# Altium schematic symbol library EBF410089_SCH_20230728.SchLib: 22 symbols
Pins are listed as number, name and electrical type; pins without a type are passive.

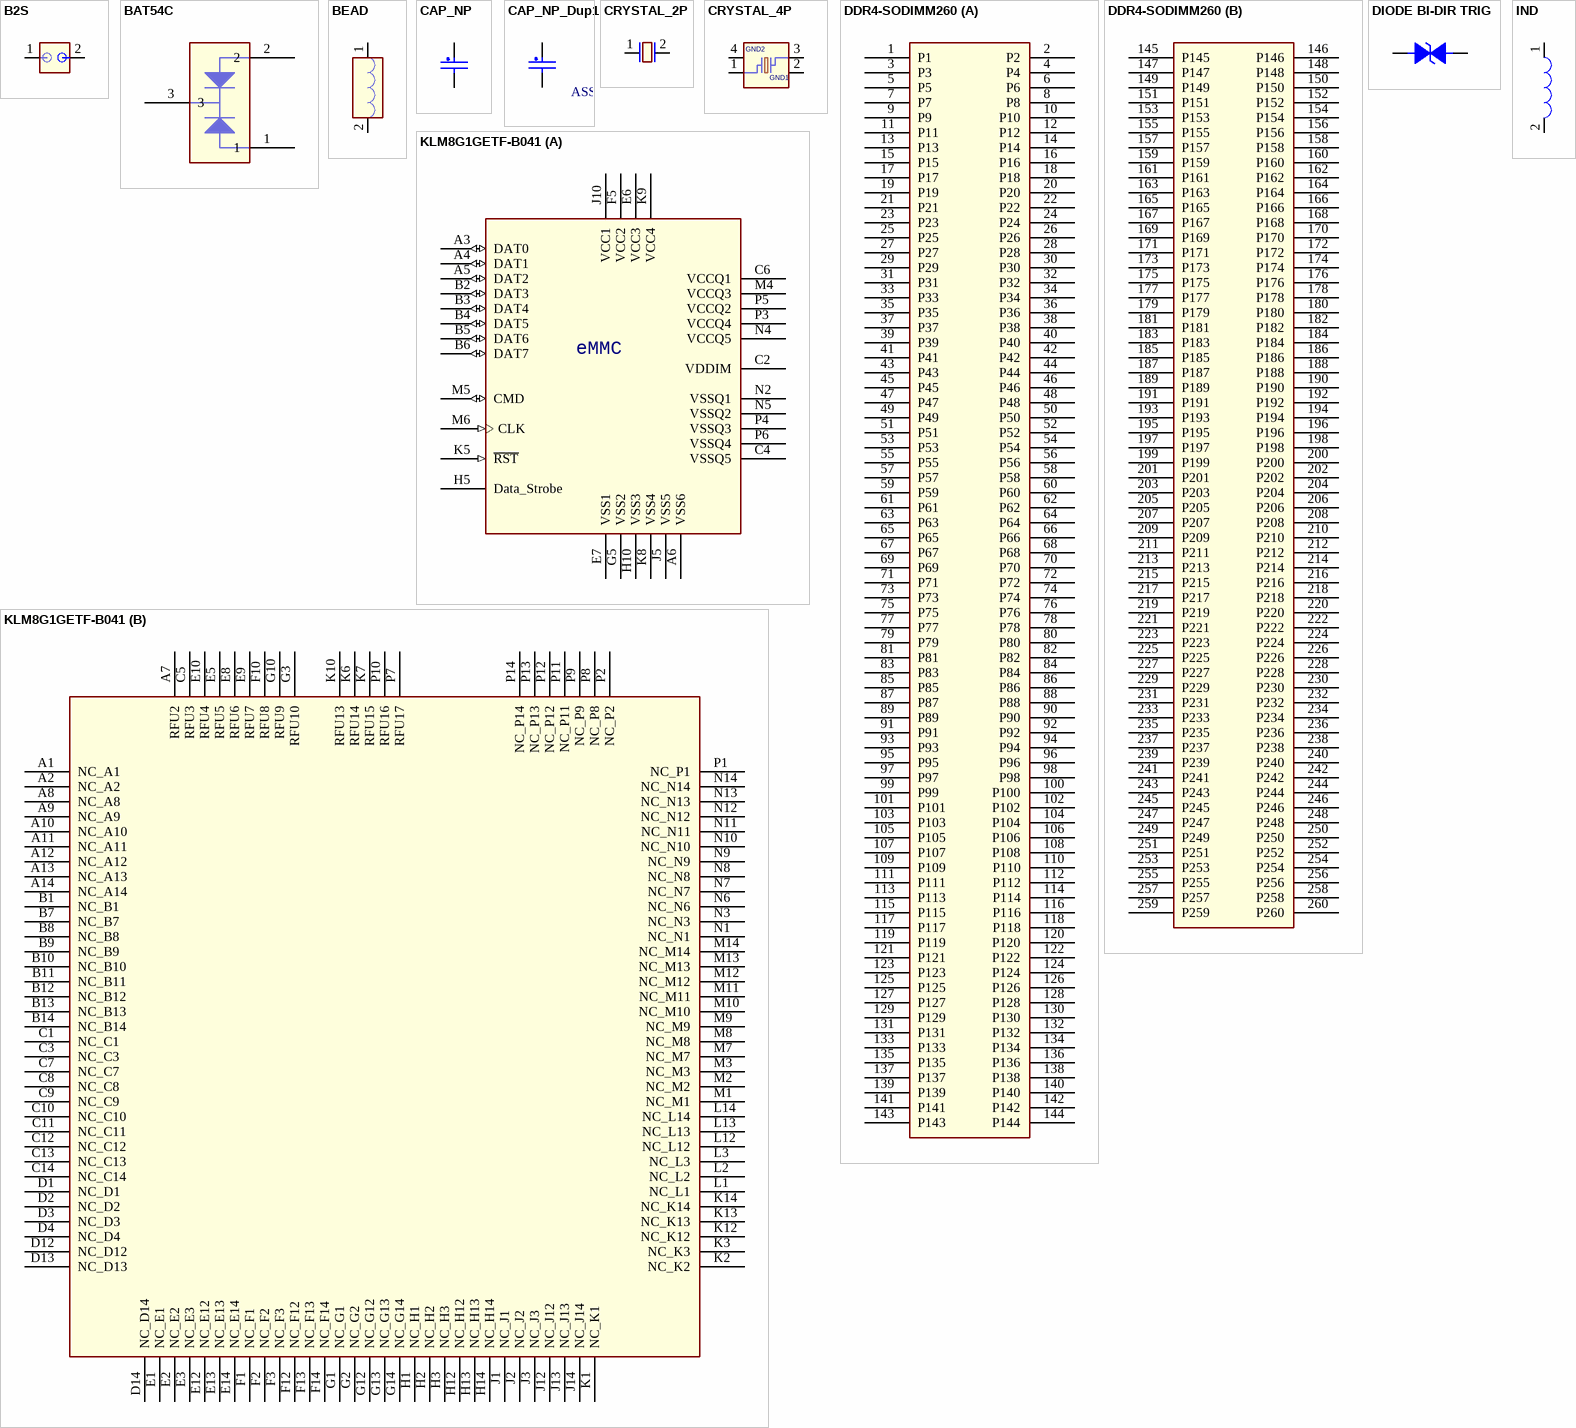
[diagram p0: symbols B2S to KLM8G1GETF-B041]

## B2S
designator J?
pins: 1, 2

## BAT54C
designator D?
footprint SOT23
pins: 1, 2, 3

## BEAD
designator L?
CLASS: DISCRETE
pins: 1, 2

## CAP_NP
designator C?
CLASS: DISCRETE
pins: 1, 2

## CAP_NP_Dup1
designator C?
CLASS: DISCRETE
pins: 1, 2

## CRYSTAL_2P
designator Y?
footprint 3215
pins: 1, 2

## CRYSTAL_4P
designator Y?
CLASS: IC
pins: 1, 2 GND1 (power), 3, 4 GND2 (power)

## DDR4-SODIMM260
designator J?
footprint SODIMMDDR4_260_0p5
part A pins: 1 P1, 2 P2, 3 P3, 4 P4, 5 P5, 6 P6, 7 P7, 8 P8, 9 P9, 10 P10, 11 P11, 12 P12, 13 P13, 14 P14, 15 P15, 16 P16, 17 P17, 18 P18, 19 P19, 20 P20, 21 P21, 22 P22, 23 P23, 24 P24, 25 P25, 26 P26, 27 P27, 28 P28, 29 P29, 30 P30, 31 P31, 32 P32, 33 P33, 34 P34, 35 P35, 36 P36, 37 P37, 38 P38, 39 P39, 40 P40, 41 P41, 42 P42, 43 P43, 44 P44, 45 P45, 46 P46, 47 P47, 48 P48, 49 P49, 50 P50, 51 P51, 52 P52, 53 P53, 54 P54, 55 P55, 56 P56, 57 P57, 58 P58, 59 P59, 60 P60, 61 P61, 62 P62, 63 P63, 64 P64, 65 P65, 66 P66, 67 P67, 68 P68, 69 P69, 70 P70, 71 P71, 72 P72, 73 P73, 74 P74, 75 P75, 76 P76, 77 P77, 78 P78, 79 P79, 80 P80, 81 P81, 82 P82, 83 P83, 84 P84, 85 P85, 86 P86, 87 P87, 88 P88, 89 P89, 90 P90, 91 P91, 92 P92, 93 P93, 94 P94, 95 P95, 96 P96, 97 P97, 98 P98, 99 P99, 100 P100, 101 P101, 102 P102, 103 P103, 104 P104, 105 P105, 106 P106, 107 P107, 108 P108, 109 P109, 110 P110, 111 P111, 112 P112, 113 P113, 114 P114, 115 P115, 116 P116, 117 P117, 118 P118, 119 P119, 120 P120, 121 P121, 122 P122, 123 P123, 124 P124, 125 P125, 126 P126, 127 P127, 128 P128, 129 P129, 130 P130, 131 P131, 132 P132, 133 P133, 134 P134, 135 P135, 136 P136, 137 P137, 138 P138, 139 P139, 140 P140, 141 P141, 142 P142, 143 P143, 144 P144
part B pins: 145 P145, 146 P146, 147 P147, 148 P148, 149 P149, 150 P150, 151 P151, 152 P152, 153 P153, 154 P154, 155 P155, 156 P156, 157 P157, 158 P158, 159 P159, 160 P160, 161 P161, 162 P162, 163 P163, 164 P164, 165 P165, 166 P166, 167 P167, 168 P168, 169 P169, 170 P170, 171 P171, 172 P172, 173 P173, 174 P174, 175 P175, 176 P176, 177 P177, 178 P178, 179 P179, 180 P180, 181 P181, 182 P182, 183 P183, 184 P184, 185 P185, 186 P186, 187 P187, 188 P188, 189 P189, 190 P190, 191 P191, 192 P192, 193 P193, 194 P194, 195 P195, 196 P196, 197 P197, 198 P198, 199 P199, 200 P200, 201 P201, 202 P202, 203 P203, 204 P204, 205 P205, 206 P206, 207 P207, 208 P208, 209 P209, 210 P210, 211 P211, 212 P212, 213 P213, 214 P214, 215 P215, 216 P216, 217 P217, 218 P218, 219 P219, 220 P220, 221 P221, 222 P222, 223 P223, 224 P224, 225 P225, 226 P226, 227 P227, 228 P228, 229 P229, 230 P230, 231 P231, 232 P232, 233 P233, 234 P234, 235 P235, 236 P236, 237 P237, 238 P238, 239 P239, 240 P240, 241 P241, 242 P242, 243 P243, 244 P244, 245 P245, 246 P246, 247 P247, 248 P248, 249 P249, 250 P250, 251 P251, 252 P252, 253 P253, 254 P254, 255 P255, 256 P256, 257 P257, 258 P258, 259 P259, 260 P260

## DIODE BI-DIR TRIG
designator D?
footprint D0603/SMD
pins: 1, 2

## IND
designator L?
CLASS: DISCRETE
pins: 1, 2

## KLM8G1GETF-B041
designator U?
CLASS: IC
footprint WFBGA153
part A pins: A3 DAT0 (io), A4 DAT1 (io), A5 DAT2 (io), A6 VSS6, B2 DAT3 (io), B3 DAT4 (io), B4 DAT5 (io), B5 DAT6 (io), B6 DAT7 (io), C2 VDDIM (power), C4 VSSQ5 (power), C6 VCCQ1 (power), E6 VCC3 (power), E7 VSS1 (power), F5 VCC2 (power), G5 VSS2 (power), H5 Data_Strobe, H10 VSS3 (power), J5 VSS5, J10 VCC1 (power), K5 ~{RST} (in), K8 VSS4 (power), K9 VCC4 (power), M4 VCCQ3 (power), M5 CMD (io), M6 CLK (in), N2 VSSQ1 (power), N4 VCCQ5 (power), N5 VSSQ2 (power), P3 VCCQ4 (power), P4 VSSQ3 (power), P5 VCCQ2 (power), P6 VSSQ4 (power)
part B pins: A1 NC_A1, A2 NC_A2, A7 RFU2, A8 NC_A8, A9 NC_A9, A10 NC_A10, A11 NC_A11, A12 NC_A12, A13 NC_A13, A14 NC_A14, B1 NC_B1, B7 NC_B7, B8 NC_B8, B9 NC_B9, B10 NC_B10, B11 NC_B11, B12 NC_B12, B13 NC_B13, B14 NC_B14, C1 NC_C1, C3 NC_C3, C5 RFU3, C7 NC_C7, C8 NC_C8, C9 NC_C9, C10 NC_C10, C11 NC_C11, C12 NC_C12, C13 NC_C13, C14 NC_C14, D1 NC_D1, D2 NC_D2, D3 NC_D3, D4 NC_D4, D12 NC_D12, D13 NC_D13, D14 NC_D14, E1 NC_E1, E2 NC_E2, E3 NC_E3, E5 RFU5, E8 RFU6, E9 RFU7, E10 RFU4, E12 NC_E12, E13 NC_E13, E14 NC_E14, F1 NC_F1, F2 NC_F2, F3 NC_F3, F10 RFU8, F12 NC_F12, F13 NC_F13, F14 NC_F14, G1 NC_G1, G2 NC_G2, G3 RFU10, G10 RFU9, G12 NC_G12, G13 NC_G13, G14 NC_G14, H1 NC_H1, H2 NC_H2, H3 NC_H3, H12 NC_H12, H13 NC_H13, H14 NC_H14, J1 NC_J1, J2 NC_J2, J3 NC_J3, J12 NC_J12, J13 NC_J13, J14 NC_J14, K1 NC_K1, K2 NC_K2, K3 NC_K3, K6 RFU14, K7 RFU15, K10 RFU13, K12 NC_K12, K13 NC_K13, K14 NC_K14, L1 NC_L1, L2 NC_L2, L3 NC_L3, L12 NC_L12, L13 NC_L13, L14 NC_L14, M1 NC_M1, M2 NC_M2, M3 NC_M3, M7 NC_M7, M8 NC_M8, M9 NC_M9, M10 NC_M10, M11 NC_M11, M12 NC_M12, M13 NC_M13, M14 NC_M14, N1 NC_N1, N3 NC_N3, N6 NC_N6, N7 NC_N7, N8 NC_N8, N9 NC_N9, N10 NC_N10, N11 NC_N11, N12 NC_N12, N13 NC_N13, N14 NC_N14, P1 NC_P1, P2 NC_P2, P7 RFU17, P8 NC_P8, P9 NC_P9, P10 RFU16, P11 NC_P11, P12 NC_P12, P13 NC_P13, P14 NC_P14

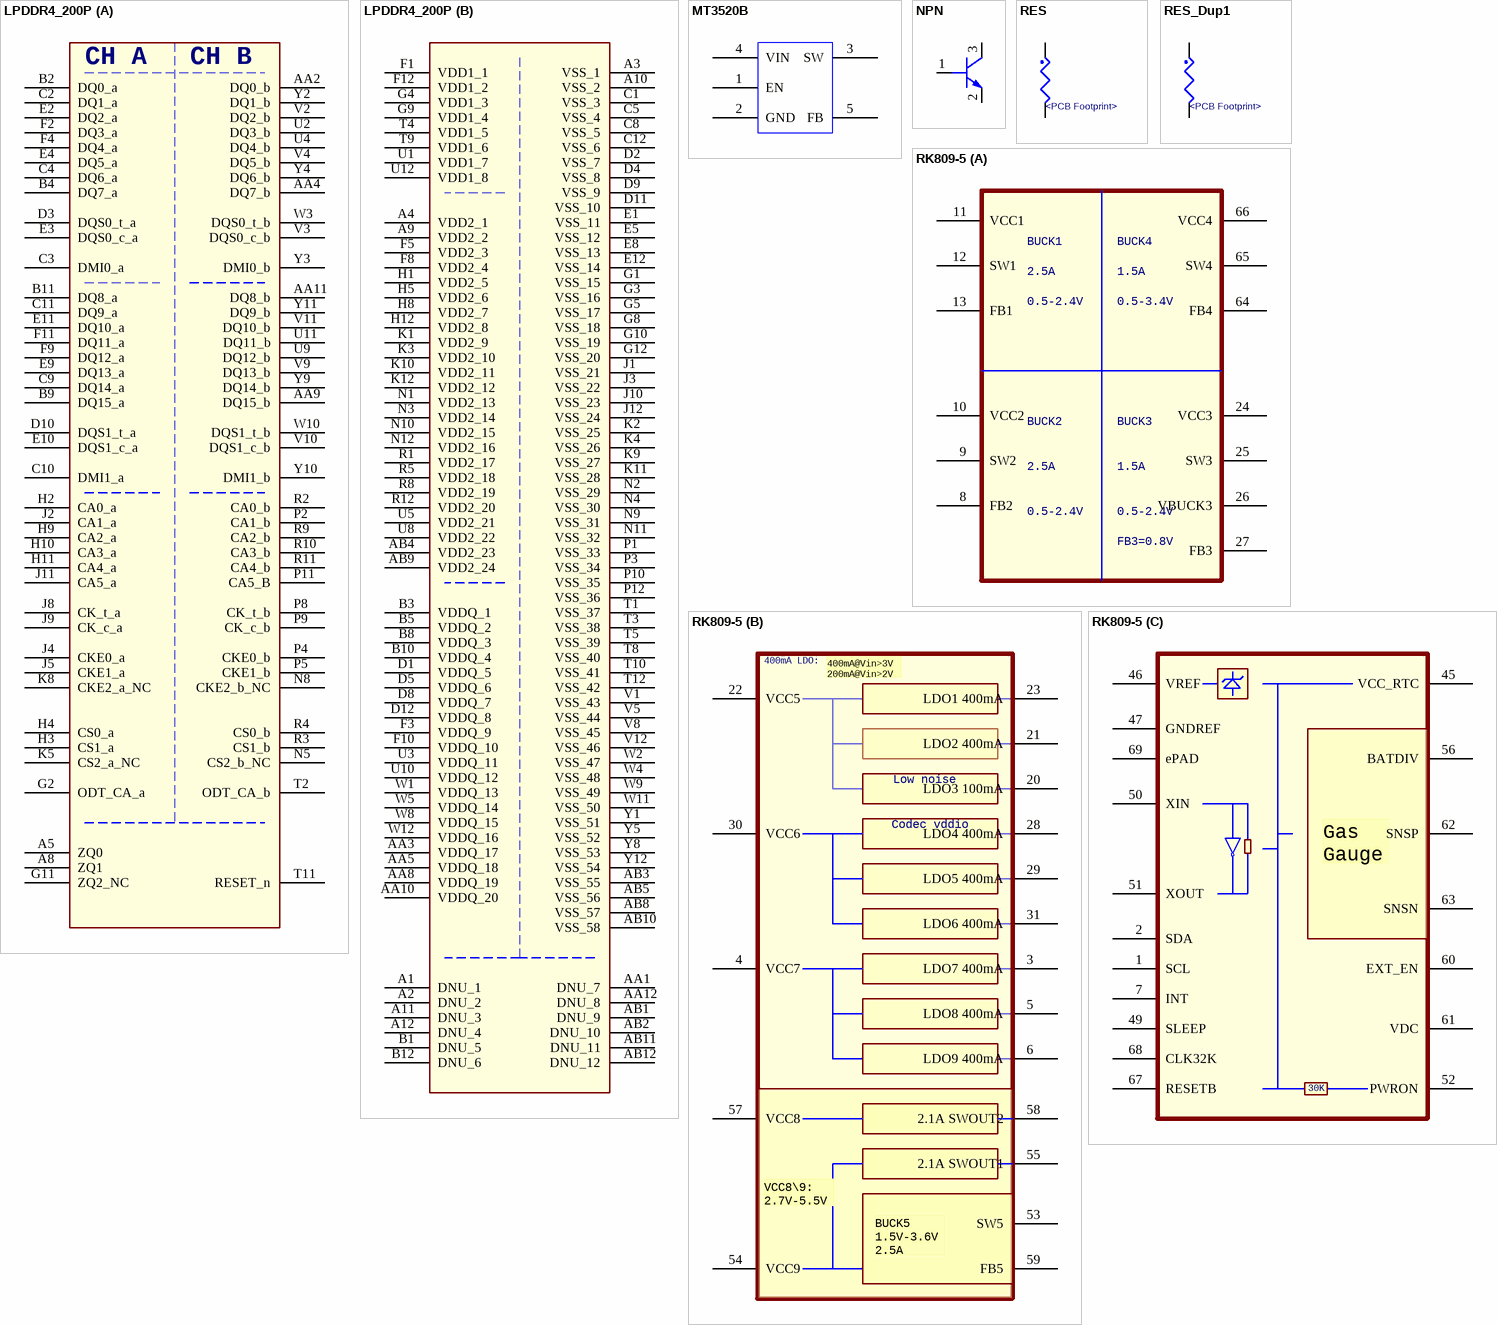
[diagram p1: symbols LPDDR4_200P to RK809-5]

## LPDDR4_200P
designator U?
part A pins: A5 ZQ0, A8 ZQ1, AA2 DQ0_b, AA4 DQ7_b, AA9 DQ15_b, AA11 DQ8_b, B2 DQ0_a, B4 DQ7_a, B9 DQ15_a, B11 DQ8_a, C2 DQ1_a, C3 DMI0_a, C4 DQ6_a, C9 DQ14_a, C10 DMI1_a, C11 DQ9_a, D3 DQS0_t_a, D10 DQS1_t_a, E2 DQ2_a, E3 DQS0_c_a, E4 DQ5_a, E9 DQ13_a, E10 DQS1_c_a, E11 DQ10_a, F2 DQ3_a, F4 DQ4_a, F9 DQ12_a, F11 DQ11_a, G2 ODT_CA_a, G11 ZQ2_NC, H2 CA0_a, H3 CS1_a, H4 CS0_a, H9 CA2_a, H10 CA3_a, H11 CA4_a, J2 CA1_a, J4 CKE0_a, J5 CKE1_a, J8 CK_t_a, J9 CK_c_a, J11 CA5_a, K5 CS2_a_NC, K8 CKE2_a_NC, N5 CS2_b_NC, N8 CKE2_b_NC, P2 CA1_b, P4 CKE0_b, P5 CKE1_b, P8 CK_t_b, P9 CK_c_b, P11 CA5_B, R2 CA0_b, R3 CS1_b, R4 CS0_b, R9 CA2_b, R10 CA3_b, R11 CA4_b, T2 ODT_CA_b, T11 RESET_n, U2 DQ3_b, U4 DQ4_b, U9 DQ12_b, U11 DQ11_b, V2 DQ2_b, V3 DQS0_c_b, V4 DQ5_b, V9 DQ13_b, V10 DQS1_c_b, V11 DQ10_b, W3 DQS0_t_b, W10 DQS1_t_b, Y2 DQ1_b, Y3 DMI0_b, Y4 DQ6_b, Y9 DQ14_b, Y10 DMI1_b, Y11 DQ9_b
part B pins: A1 DNU_1, A2 DNU_2, A3 VSS_1 (power), A4 VDD2_1 (power), A9 VDD2_2 (power), A10 VSS_2 (power), A11 DNU_3, A12 DNU_4, AA1 DNU_7, AA3 VDDQ_17 (power), AA5 VDDQ_18 (power), AA8 VDDQ_19 (power), AA10 VDDQ_20 (power), AA12 DNU_8, AB1 DNU_9, AB2 DNU_10, AB3 VSS_55 (power), AB4 VDD2_23 (power), AB5 VSS_56 (power), AB8 VSS_57 (power), AB9 VDD2_24 (power), AB10 VSS_58 (power), AB11 DNU_11, AB12 DNU_12, B1 DNU_5, B3 VDDQ_1 (power), B5 VDDQ_2 (power), B8 VDDQ_3 (power), B10 VDDQ_4 (power), B12 DNU_6, C1 VSS_3 (power), C5 VSS_4 (power), C8 VSS_5 (power), C12 VSS_6 (power), D1 VDDQ_5 (power), D2 VSS_7 (power), D4 VSS_8 (power), D5 VDDQ_6 (power), D8 VDDQ_7 (power), D9 VSS_9 (power), D11 VSS_10 (power), D12 VDDQ_8 (power), E1 VSS_11 (power), E5 VSS_12 (power), E8 VSS_13 (power), E12 VSS_14 (power), F1 VDD1_1 (power), F3 VDDQ_9 (power), F5 VDD2_3 (power), F8 VDD2_4 (power), F10 VDDQ_10 (power), F12 VDD1_2 (power), G1 VSS_15 (power), G3 VSS_16 (power), G4 VDD1_3 (power), G5 VSS_17 (power), G8 VSS_18 (power), G9 VDD1_4 (power), G10 VSS_19 (power), G12 VSS_20 (power), H1 VDD2_5 (power), H5 VDD2_6 (power), H8 VDD2_7 (power), H12 VDD2_8 (power), J1 VSS_21 (power), J3 VSS_22 (power), J10 VSS_23 (power), J12 VSS_24 (power), K1 VDD2_9 (power), K2 VSS_25 (power), K3 VDD2_10 (power), K4 VSS_26 (power), K9 VSS_27 (power), K10 VDD2_11 (power), K11 VSS_28 (power), K12 VDD2_12 (power), N1 VDD2_13 (power), N2 VSS_29 (power), N3 VDD2_14 (power), N4 VSS_30 (power), N9 VSS_31 (power), N10 VDD2_15 (power), N11 VSS_32 (power), N12 VDD2_16 (power), P1 VSS_33 (power), P3 VSS_34 (power), P10 VSS_35 (power), P12 VSS_36 (power), R1 VDD2_17 (power), R5 VDD2_18 (power), R8 VDD2_19 (power), R12 VDD2_20 (power), T1 VSS_37 (power), T3 VSS_38 (power), T4 VDD1_5 (power), T5 VSS_39 (power), T8 VSS_40 (power), T9 VDD1_6 (power), T10 VSS_41 (power), T12 VSS_42 (power), U1 VDD1_7 (power), U3 VDDQ_11 (power), U5 VDD2_21 (power), U8 VDD2_22 (power), U10 VDDQ_12 (power), U12 VDD1_8 (power), V1 VSS_43 (power), V5 VSS_44 (power), V8 VSS_45 (power), V12 VSS_46 (power), W1 VDDQ_13 (power), W2 VSS_47 (power), W4 VSS_48 (power), W5 VDDQ_14 (power), W8 VDDQ_15 (power), W9 VSS_49 (power), W11 VSS_50 (power), W12 VDDQ_16 (power), Y1 VSS_51 (power), Y5 VSS_52 (power), Y8 VSS_53 (power), Y12 VSS_54 (power)

## MT3520B
designator U?
footprint sot_23_5
pins: 1 EN, 2 GND, 3 SW, 4 VIN, 5 FB

## NPN
designator Q?
pins: 1 BASE, 2 EMITTER, 3 COLLECTOR

## RES
designator R?  PCB Footprint: <PCB Footprint>
CLASS: DISCRETE
pins: 1, 2

## RES_Dup1
designator R?  PCB Footprint: <PCB Footprint>
CLASS: DISCRETE
pins: 1, 2

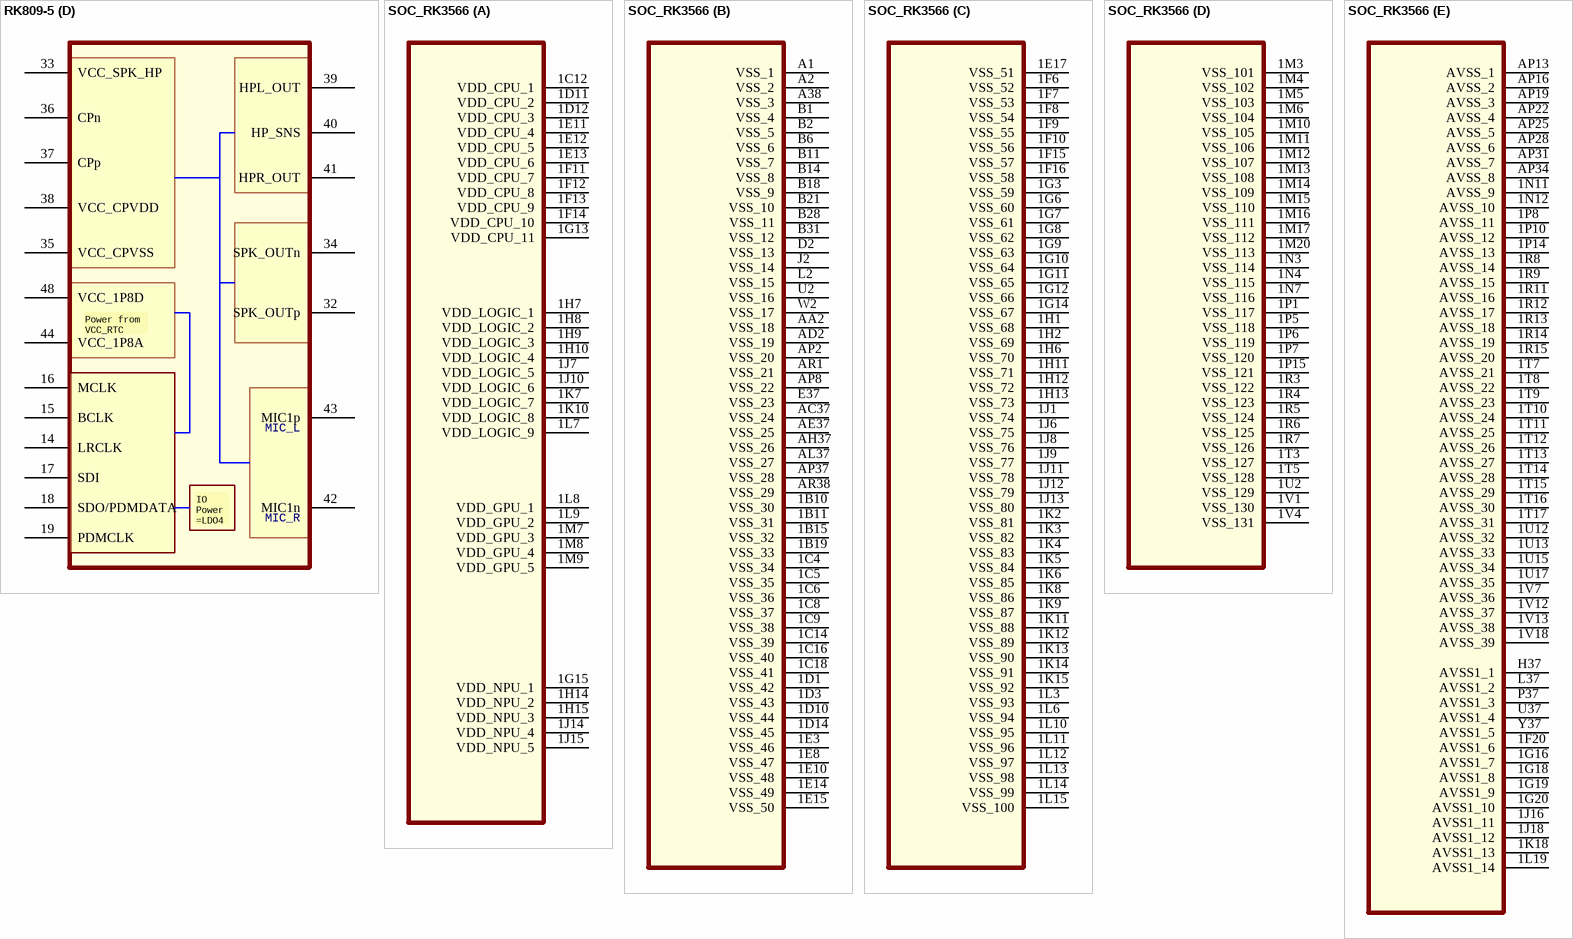
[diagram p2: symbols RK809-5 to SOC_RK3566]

## RK809-5
designator U?
footprint QFN68_7R00X7R00X0R80_T
part A pins: 8 FB2, 9 SW2, 10 VCC2, 11 VCC1, 12 SW1, 13 FB1, 24 VCC3, 25 SW3, 26 VBUCK3, 27 FB3, 64 FB4, 65 SW4, 66 VCC4
part B pins: 3 LDO7 400mA, 4 VCC7, 5 LDO8 400mA, 6 LDO9 400mA, 20 LDO3 100mA, 21 LDO2 400mA, 22 VCC5, 23 LDO1 400mA, 28 LDO4 400mA, 29 LDO5 400mA, 30 VCC6, 31 LDO6 400mA, 53 SW5, 54 VCC9, 55 2.1A SWOUT1, 57 VCC8, 58 2.1A SWOUT2, 59 FB5
part C pins: 1 SCL, 2 SDA, 7 INT, 45 VCC_RTC, 46 VREF, 47 GNDREF, 49 SLEEP, 50 XIN, 51 XOUT, 52 PWRON, 56 BATDIV, 60 EXT_EN, 61 VDC, 62 SNSP, 63 SNSN, 67 RESETB, 68 CLK32K, 69 ePAD
part D pins: 14 LRCLK, 15 BCLK, 16 MCLK, 17 SDI, 18 SDO/PDMDATA, 19 PDMCLK, 32 SPK_OUTp, 33 VCC_SPK_HP, 34 SPK_OUTn, 35 VCC_CPVSS, 36 CPn, 37 CPp, 38 VCC_CPVDD, 39 HPL_OUT, 40 HP_SNS, 41 HPR_OUT, 42 MIC1n, 43 MIC1p, 44 VCC_1P8A, 48 VCC_1P8D

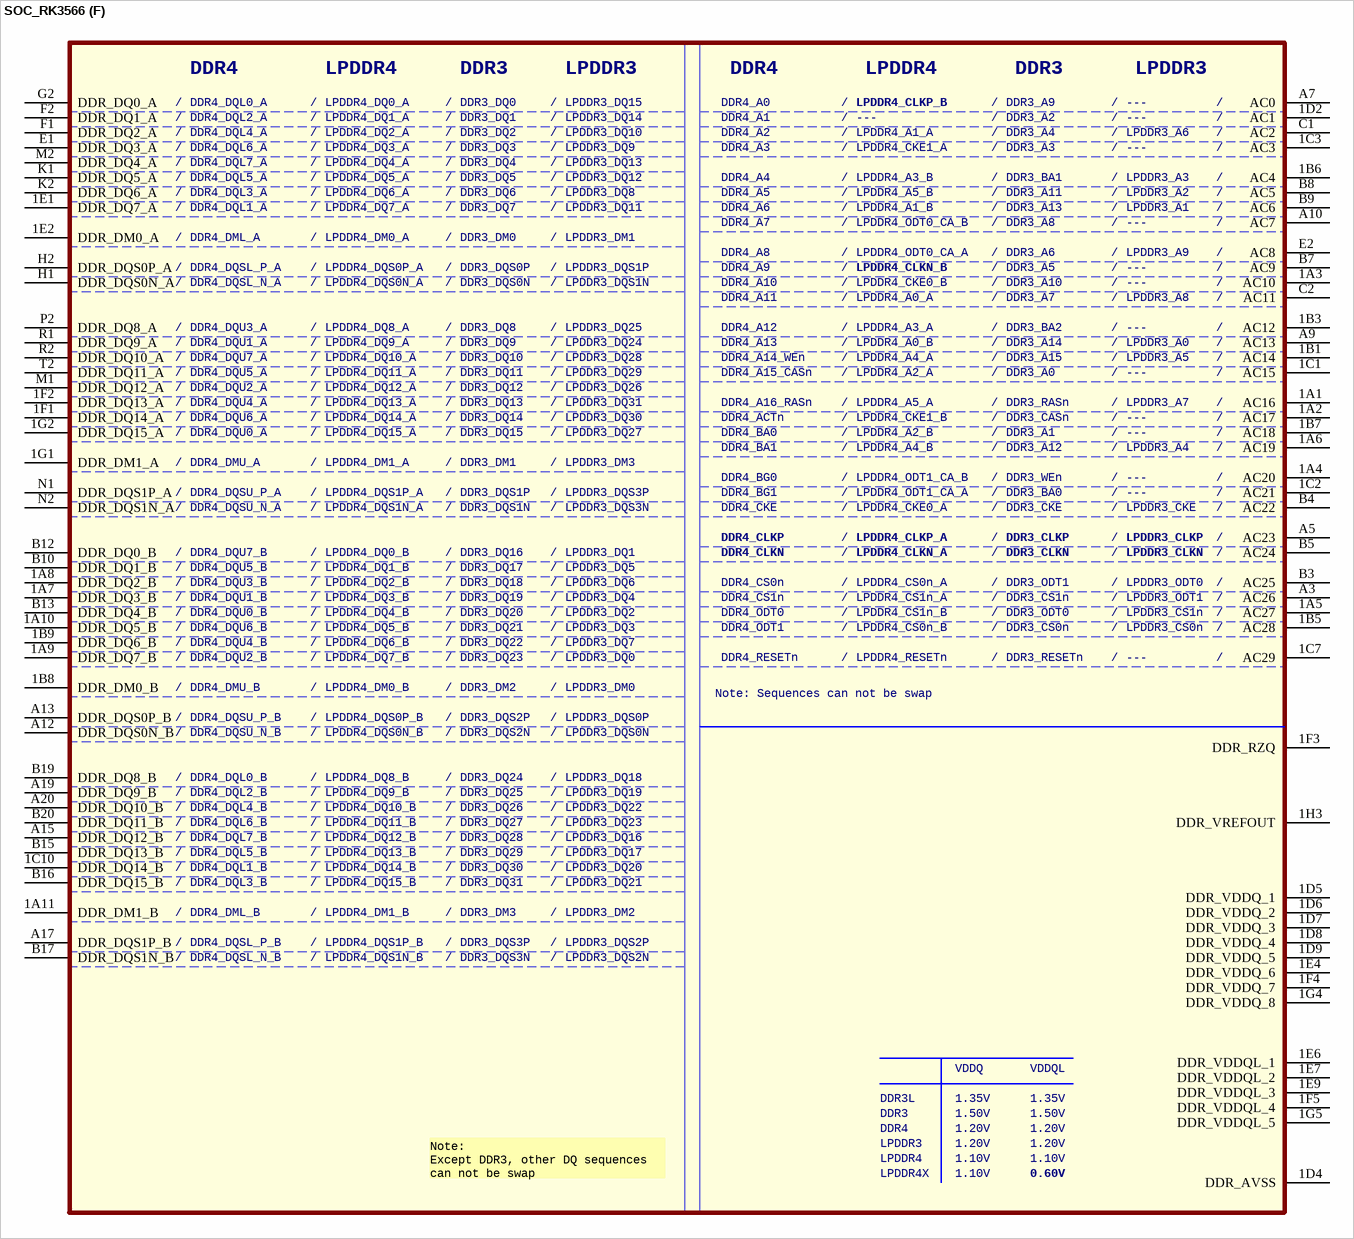
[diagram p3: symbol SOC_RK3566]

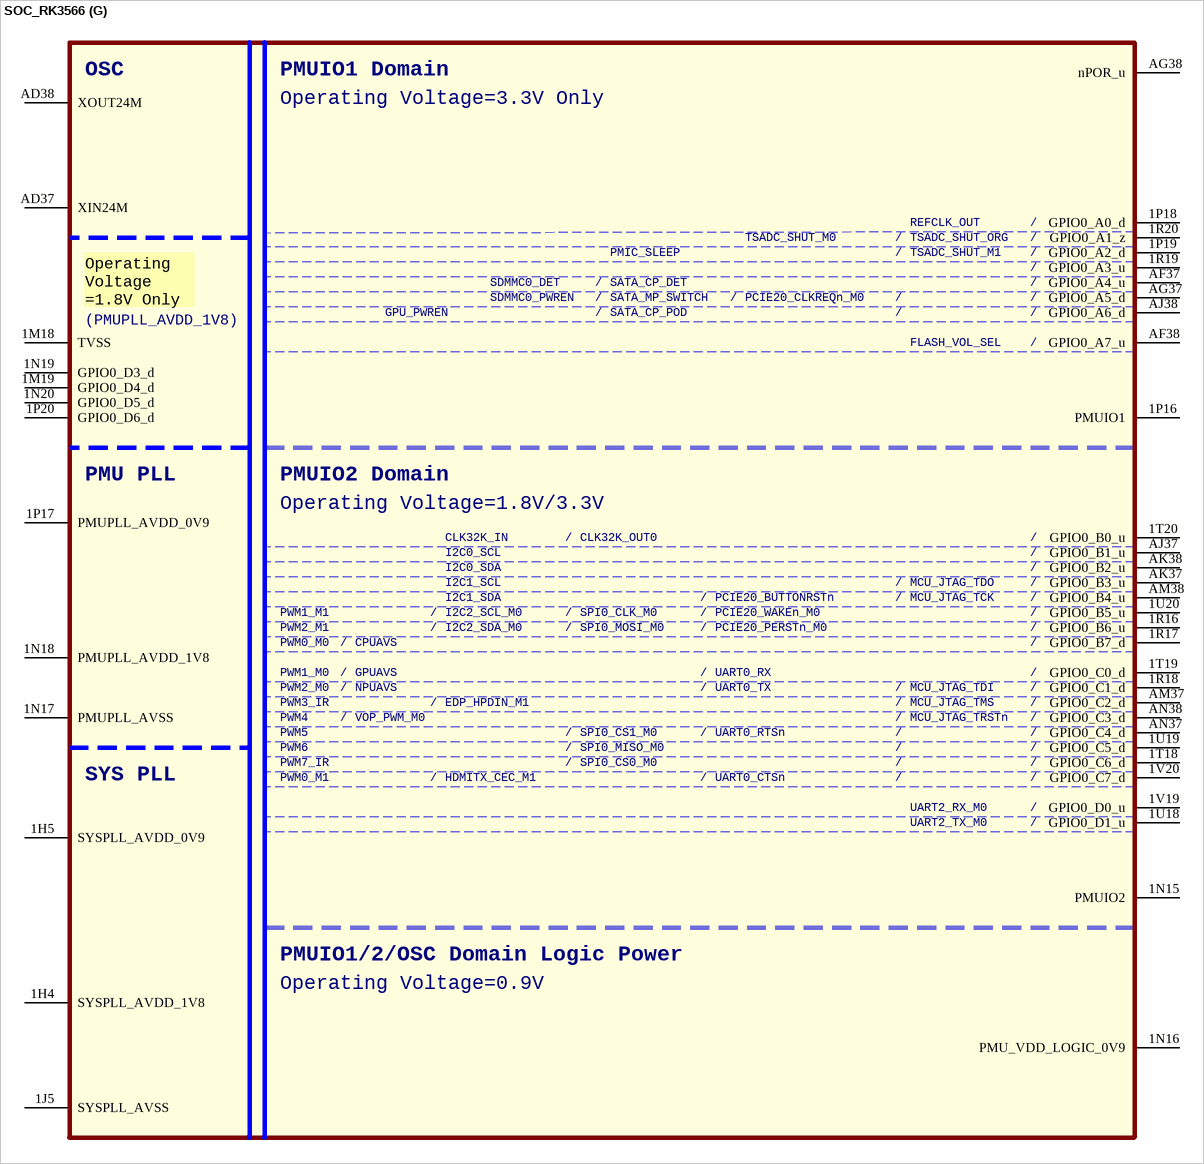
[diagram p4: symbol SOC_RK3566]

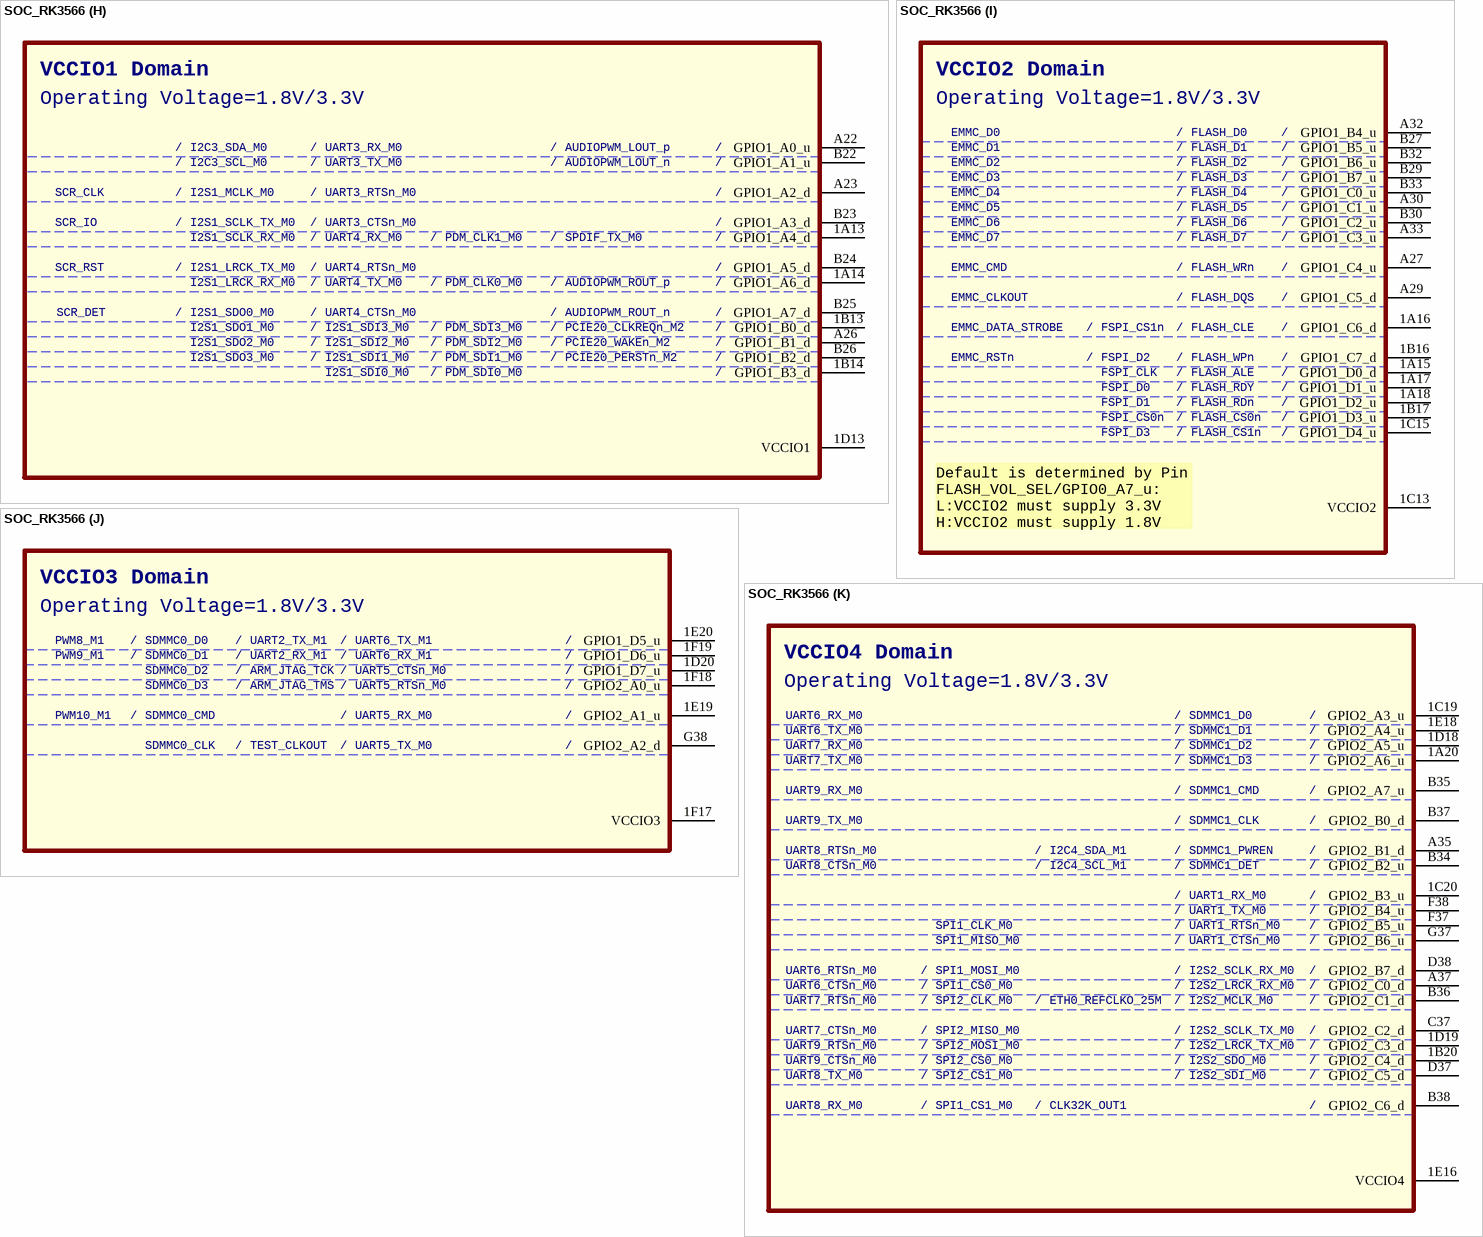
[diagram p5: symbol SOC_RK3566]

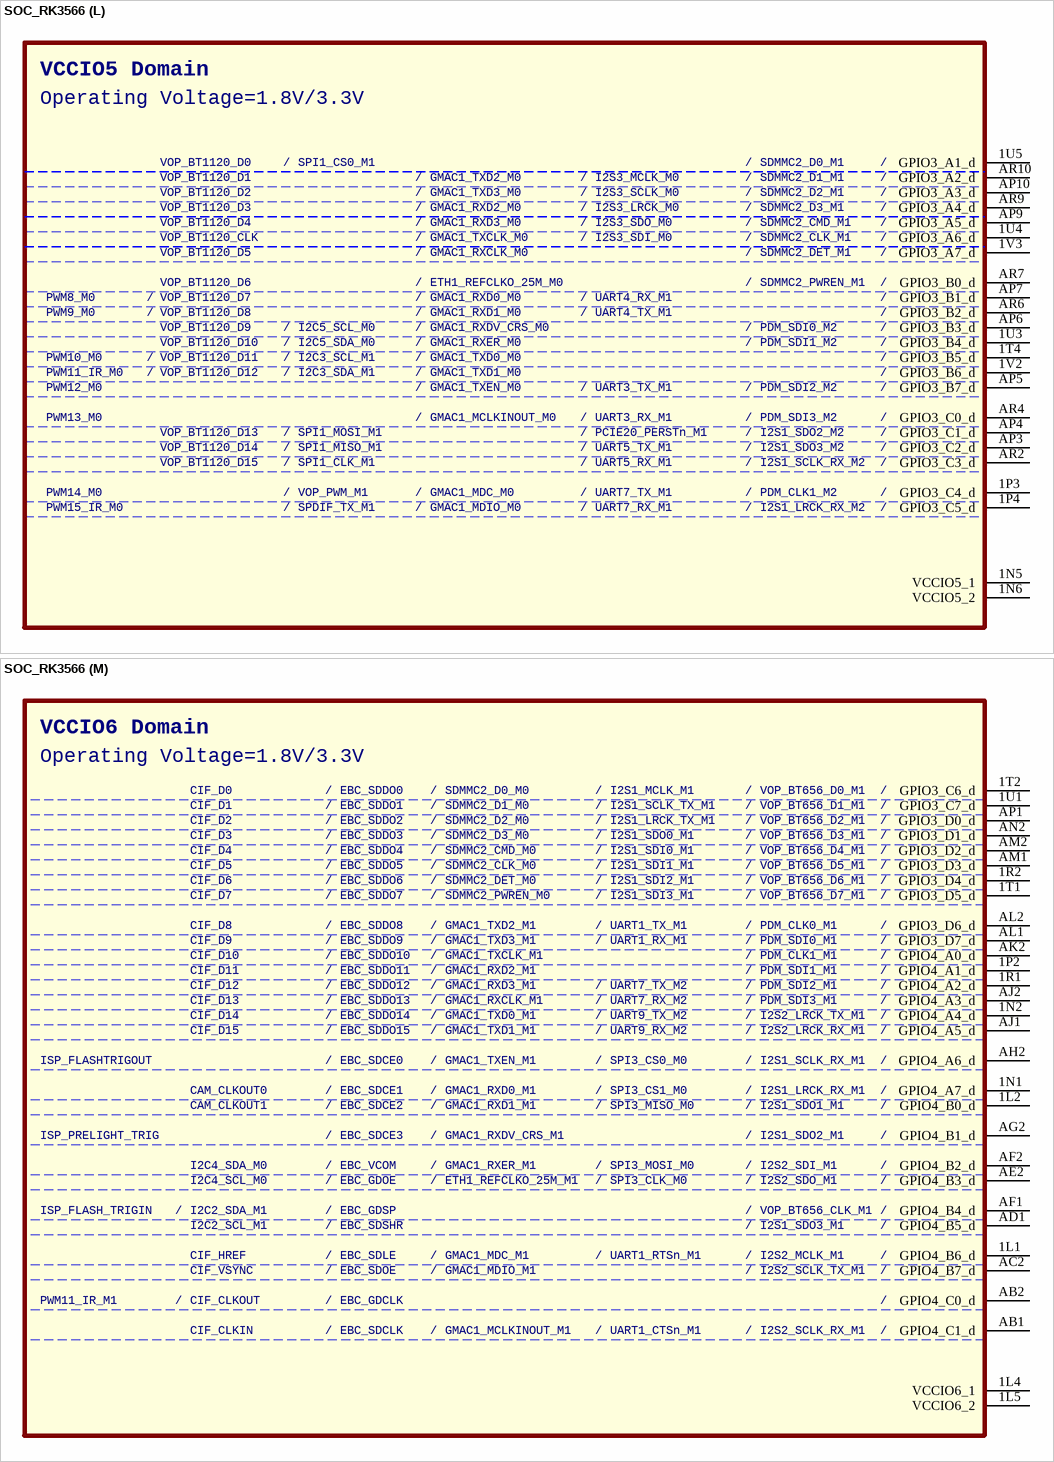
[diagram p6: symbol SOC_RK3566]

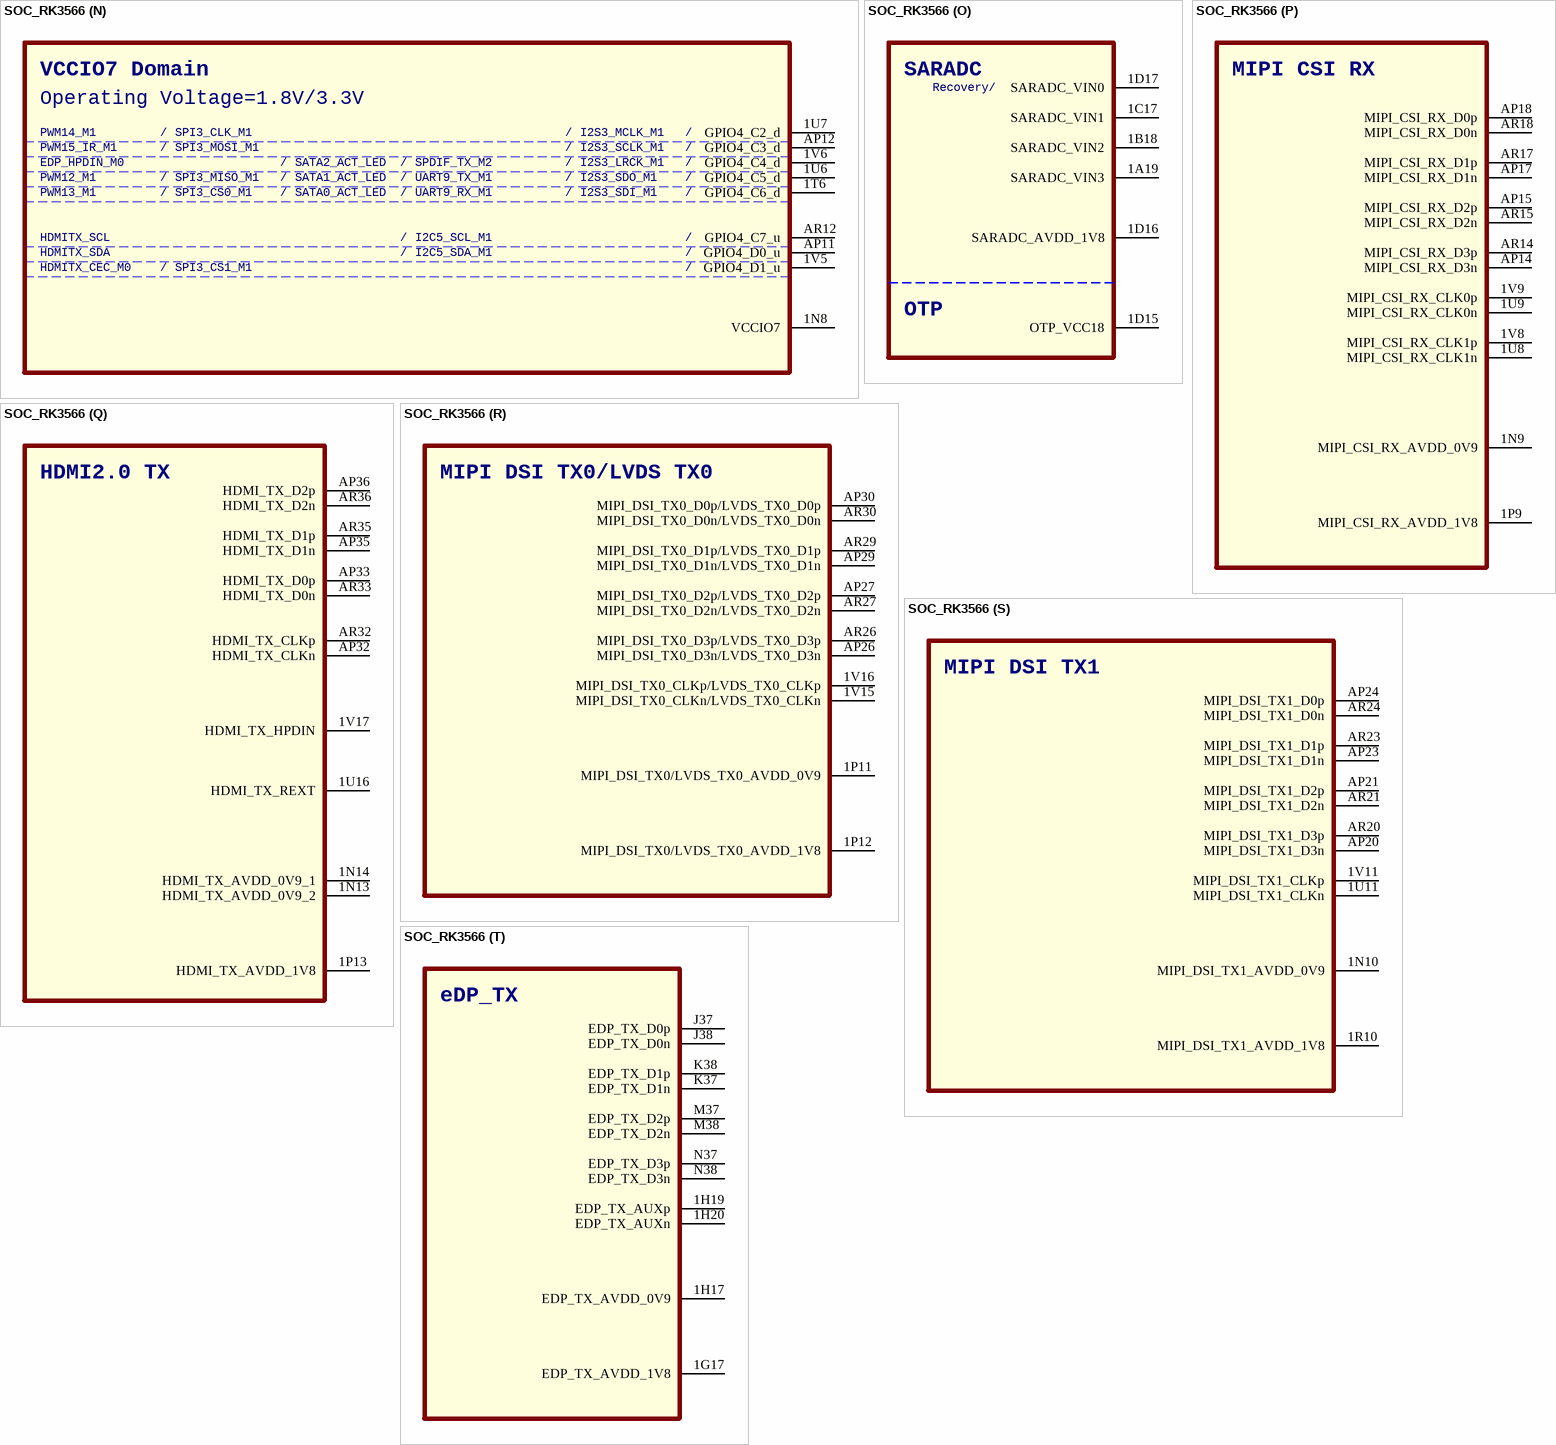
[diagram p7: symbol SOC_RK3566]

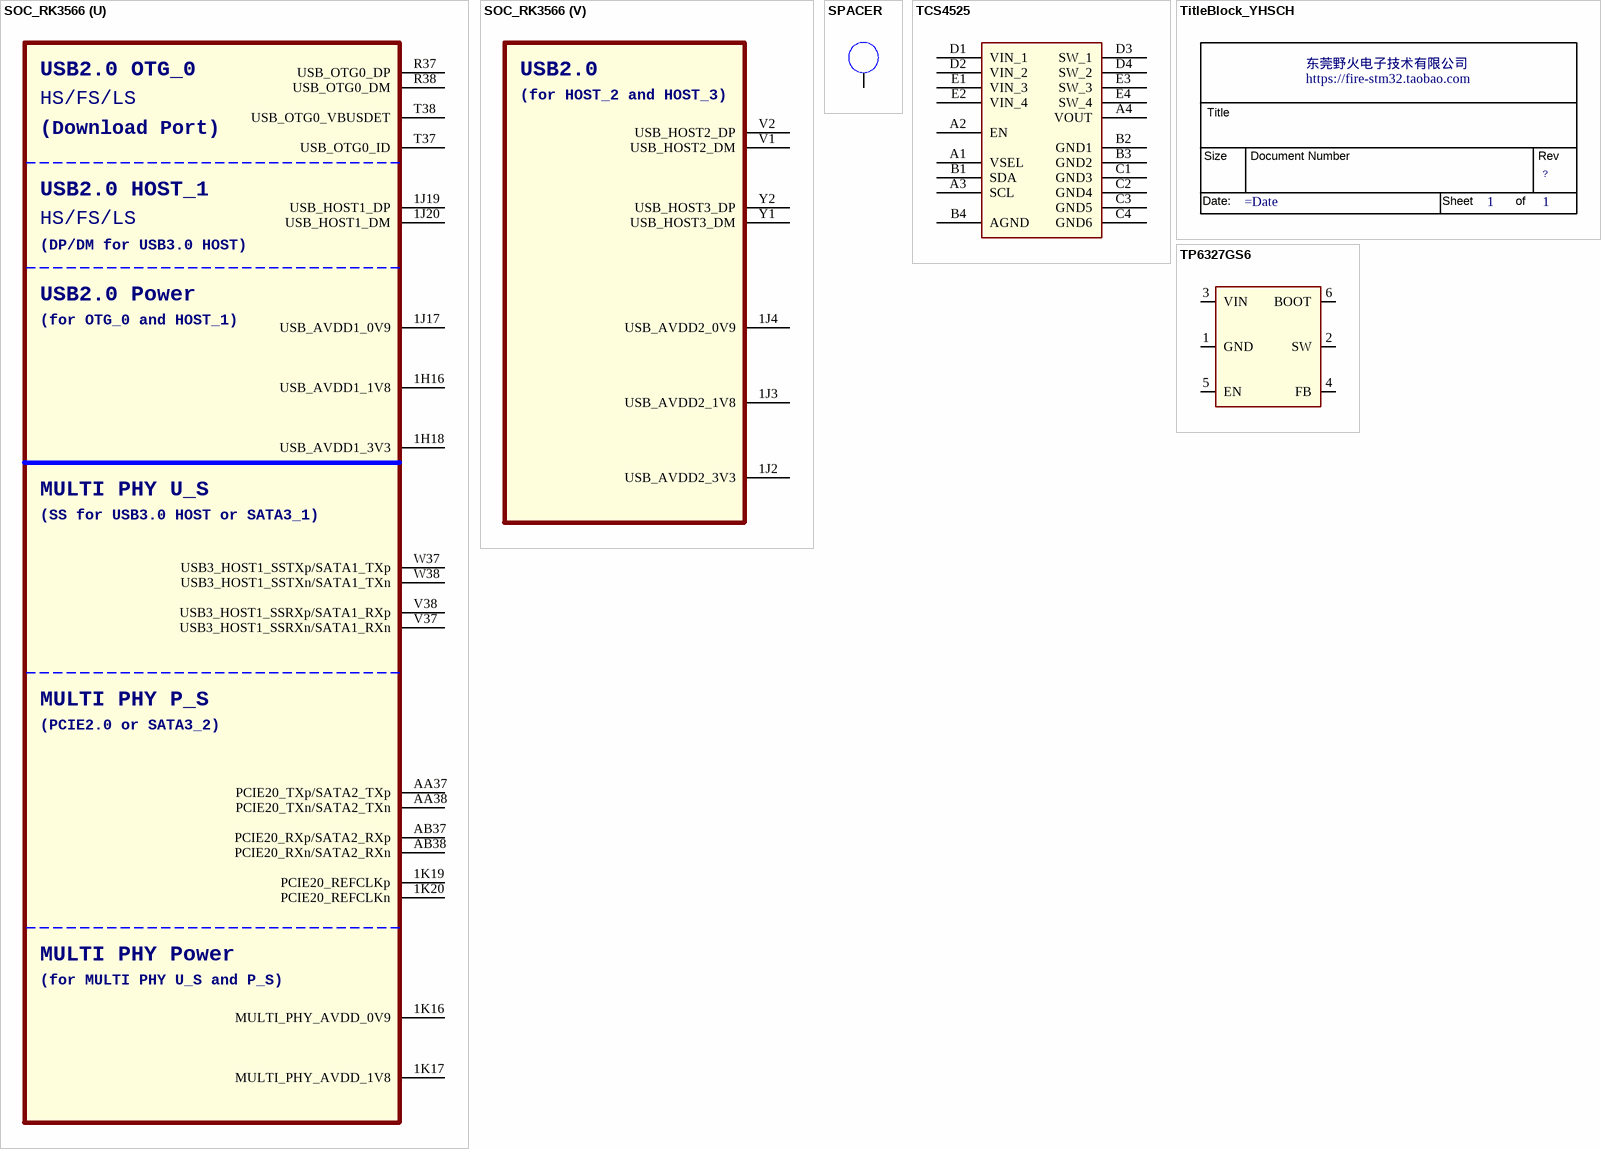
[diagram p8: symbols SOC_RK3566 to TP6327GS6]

## SOC_RK3566
designator U?
SPLIT_INST: TRUE; SWAP_INFO: (S1+S2+S3+S4+S5+S6+S7+S8+S9+S10+S11+S12+S13+S14+S15+S16+S17+S18+S19+S20+S21+S22+S23)
part A pins: 1C12 VDD_CPU_1, 1D11 VDD_CPU_2, 1D12 VDD_CPU_3, 1E11 VDD_CPU_4, 1E12 VDD_CPU_5, 1E13 VDD_CPU_6, 1F11 VDD_CPU_7, 1F12 VDD_CPU_8, 1F13 VDD_CPU_9, 1F14 VDD_CPU_10, 1G13 VDD_CPU_11, 1G15 VDD_NPU_1, 1H7 VDD_LOGIC_1, 1H8 VDD_LOGIC_2, 1H9 VDD_LOGIC_3, 1H10 VDD_LOGIC_4, 1H14 VDD_NPU_2, 1H15 VDD_NPU_3, 1J7 VDD_LOGIC_5, 1J10 VDD_LOGIC_6, 1J14 VDD_NPU_4, 1J15 VDD_NPU_5, 1K7 VDD_LOGIC_7, 1K10 VDD_LOGIC_8, 1L7 VDD_LOGIC_9, 1L8 VDD_GPU_1, 1L9 VDD_GPU_2, 1M7 VDD_GPU_3, 1M8 VDD_GPU_4, 1M9 VDD_GPU_5
part B pins: 1B10 VSS_30, 1B11 VSS_31, 1B15 VSS_32, 1B19 VSS_33, 1C4 VSS_34, 1C5 VSS_35, 1C6 VSS_36, 1C8 VSS_37, 1C9 VSS_38, 1C14 VSS_39, 1C16 VSS_40, 1C18 VSS_41, 1D1 VSS_42, 1D3 VSS_43, 1D10 VSS_44, 1D14 VSS_45, 1E3 VSS_46, 1E8 VSS_47, 1E10 VSS_48, 1E14 VSS_49, 1E15 VSS_50, A1 VSS_1, A2 VSS_2, A38 VSS_3, AA2 VSS_18, AC37 VSS_24, AD2 VSS_19, AE37 VSS_25, AH37 VSS_26, AL37 VSS_27, AP2 VSS_20, AP8 VSS_22, AP37 VSS_28, AR1 VSS_21, AR38 VSS_29, B1 VSS_4, B2 VSS_5, B6 VSS_6, B11 VSS_7, B14 VSS_8, B18 VSS_9, B21 VSS_10, B28 VSS_11, B31 VSS_12, D2 VSS_13, E37 VSS_23, J2 VSS_14, L2 VSS_15, U2 VSS_16, W2 VSS_17
part C pins: 1E17 VSS_51, 1F6 VSS_52, 1F7 VSS_53, 1F8 VSS_54, 1F9 VSS_55, 1F10 VSS_56, 1F15 VSS_57, 1F16 VSS_58, 1G3 VSS_59, 1G6 VSS_60, 1G7 VSS_61, 1G8 VSS_62, 1G9 VSS_63, 1G10 VSS_64, 1G11 VSS_65, 1G12 VSS_66, 1G14 VSS_67, 1H1 VSS_68, 1H2 VSS_69, 1H6 VSS_70, 1H11 VSS_71, 1H12 VSS_72, 1H13 VSS_73, 1J1 VSS_74, 1J6 VSS_75, 1J8 VSS_76, 1J9 VSS_77, 1J11 VSS_78, 1J12 VSS_79, 1J13 VSS_80, 1K2 VSS_81, 1K3 VSS_82, 1K4 VSS_83, 1K5 VSS_84, 1K6 VSS_85, 1K8 VSS_86, 1K9 VSS_87, 1K11 VSS_88, 1K12 VSS_89, 1K13 VSS_90, 1K14 VSS_91, 1K15 VSS_92, 1L3 VSS_93, 1L6 VSS_94, 1L10 VSS_95, 1L11 VSS_96, 1L12 VSS_97, 1L13 VSS_98, 1L14 VSS_99, 1L15 VSS_100
part D pins: 1M3 VSS_101, 1M4 VSS_102, 1M5 VSS_103, 1M6 VSS_104, 1M10 VSS_105, 1M11 VSS_106, 1M12 VSS_107, 1M13 VSS_108, 1M14 VSS_109, 1M15 VSS_110, 1M16 VSS_111, 1M17 VSS_112, 1M20 VSS_113, 1N3 VSS_114, 1N4 VSS_115, 1N7 VSS_116, 1P1 VSS_117, 1P5 VSS_118, 1P6 VSS_119, 1P7 VSS_120, 1P15 VSS_121, 1R3 VSS_122, 1R4 VSS_123, 1R5 VSS_124, 1R6 VSS_125, 1R7 VSS_126, 1T3 VSS_127, 1T5 VSS_128, 1U2 VSS_129, 1V1 VSS_130, 1V4 VSS_131
part E pins: 1F20 AVSS1_6, 1G16 AVSS1_7, 1G18 AVSS1_8, 1G19 AVSS1_9, 1G20 AVSS1_10, 1J16 AVSS1_11, 1J18 AVSS1_12, 1K18 AVSS1_13, 1L19 AVSS1_14, 1N11 AVSS_9, 1N12 AVSS_10, 1P8 AVSS_11, 1P10 AVSS_12, 1P14 AVSS_13, 1R8 AVSS_14, 1R9 AVSS_15, 1R11 AVSS_16, 1R12 AVSS_17, 1R13 AVSS_18, 1R14 AVSS_19, 1R15 AVSS_20, 1T7 AVSS_21, 1T8 AVSS_22, 1T9 AVSS_23, 1T10 AVSS_24, 1T11 AVSS_25, 1T12 AVSS_26, 1T13 AVSS_27, 1T14 AVSS_28, 1T15 AVSS_29, 1T16 AVSS_30, 1T17 AVSS_31, 1U12 AVSS_32, 1U13 AVSS_33, 1U15 AVSS_34, 1U17 AVSS_35, 1V7 AVSS_36, 1V12 AVSS_37, 1V13 AVSS_38, 1V18 AVSS_39, AP13 AVSS_1, AP16 AVSS_2, AP19 AVSS_3, AP22 AVSS_4, AP25 AVSS_5, AP28 AVSS_6, AP31 AVSS_7, AP34 AVSS_8, H37 AVSS1_1, L37 AVSS1_2, P37 AVSS1_3, U37 AVSS1_4, Y37 AVSS1_5
part F pins: 1A1 AC16, 1A2 AC17, 1A3 AC10, 1A4 AC20, 1A5 AC27, 1A6 AC19, 1A7 DDR_DQ3_B, 1A8 DDR_DQ2_B, 1A9 DDR_DQ7_B, 1A10 DDR_DQ5_B, 1A11 DDR_DM1_B, 1B1 AC14, 1B3 AC12, 1B5 AC28, 1B6 AC4, 1B7 AC18, 1B8 DDR_DM0_B, 1B9 DDR_DQ6_B, 1C1 AC15, 1C2 AC21, 1C3 AC3, 1C7 AC29, 1C10 DDR_DQ14_B, 1D2 AC1, 1D4 DDR_AVSS, 1D5 DDR_VDDQ_1, 1D6 DDR_VDDQ_2, 1D7 DDR_VDDQ_3, 1D8 DDR_VDDQ_4, 1D9 DDR_VDDQ_5, 1E1 DDR_DQ7_A, 1E2 DDR_DM0_A, 1E4 DDR_VDDQ_6, 1E6 DDR_VDDQL_1, 1E7 DDR_VDDQL_2, 1E9 DDR_VDDQL_3, 1F1 DDR_DQ14_A, 1F2 DDR_DQ13_A, 1F3 DDR_RZQ, 1F4 DDR_VDDQ_7, 1F5 DDR_VDDQL_4, 1G1 DDR_DM1_A, 1G2 DDR_DQ15_A, 1G4 DDR_VDDQ_8, 1G5 DDR_VDDQL_5, 1H3 DDR_VREFOUT, A3 AC26, A5 AC23, A7 AC0, A9 AC13, A10 AC7, A12 DDR_DQS0N_B, A13 DDR_DQS0P_B, A15 DDR_DQ12_B, A17 DDR_DQS1P_B, A19 DDR_DQ9_B, A20 DDR_DQ10_B, B3 AC25, B4 AC22, B5 AC24, B7 AC9, B8 AC5, B9 AC6, B10 DDR_DQ1_B, B12 DDR_DQ0_B, B13 DDR_DQ4_B, B15 DDR_DQ13_B, B16 DDR_DQ15_B, B17 DDR_DQS1N_B, B19 DDR_DQ8_B, B20 DDR_DQ11_B, C1 AC2, C2 AC11, E1 DDR_DQ3_A, E2 AC8, F1 DDR_DQ2_A, F2 DDR_DQ1_A, G2 DDR_DQ0_A, H1 DDR_DQS0N_A, H2 DDR_DQS0P_A, K1 DDR_DQ5_A, K2 DDR_DQ6_A, M1 DDR_DQ12_A, M2 DDR_DQ4_A, N1 DDR_DQS1P_A, N2 DDR_DQS1N_A, P2 DDR_DQ8_A, R1 DDR_DQ9_A, R2 DDR_DQ10_A, T2 DDR_DQ11_A
part G pins: 1H4 SYSPLL_AVDD_1V8, 1H5 SYSPLL_AVDD_0V9, 1J5 SYSPLL_AVSS, 1M18 TVSS, 1M19 GPIO0_D4_d, 1N15 PMUIO2, 1N16 PMU_VDD_LOGIC_0V9, 1N17 PMUPLL_AVSS, 1N18 PMUPLL_AVDD_1V8, 1N19 GPIO0_D3_d, 1N20 GPIO0_D5_d, 1P16 PMUIO1, 1P17 PMUPLL_AVDD_0V9, 1P18 GPIO0_A0_d, 1P19 GPIO0_A2_d, 1P20 GPIO0_D6_d, 1R16 GPIO0_B6_u, 1R17 GPIO0_B7_d, 1R18 GPIO0_C1_d, 1R19 GPIO0_A3_u, 1R20 GPIO0_A1_z, 1T18 GPIO0_C6_d, 1T19 GPIO0_C0_d, 1T20 GPIO0_B0_u, 1U18 GPIO0_D1_u, 1U19 GPIO0_C5_d, 1U20 GPIO0_B5_u, 1V19 GPIO0_D0_u, 1V20 GPIO0_C7_d, AD37 XIN24M, AD38 XOUT24M, AF37 GPIO0_A4_u, AF38 GPIO0_A7_u, AG37 GPIO0_A5_d, AG38 nPOR_u, AJ37 GPIO0_B1_u, AJ38 GPIO0_A6_d, AK37 GPIO0_B3_u, AK38 GPIO0_B2_u, AM37 GPIO0_C2_d, AM38 GPIO0_B4_u, AN37 GPIO0_C4_d, AN38 GPIO0_C3_d
part H pins: 1A13 GPIO1_A4_d, 1A14 GPIO1_A6_d, 1B13 GPIO1_B0_d, 1B14 GPIO1_B3_d, 1D13 VCCIO1, A22 GPIO1_A0_u, A23 GPIO1_A2_d, A26 GPIO1_B1_d, B22 GPIO1_A1_u, B23 GPIO1_A3_d, B24 GPIO1_A5_d, B25 GPIO1_A7_d, B26 GPIO1_B2_d
part I pins: 1A15 GPIO1_D0_d, 1A16 GPIO1_C6_d, 1A17 GPIO1_D1_u, 1A18 GPIO1_D2_u, 1B16 GPIO1_C7_d, 1B17 GPIO1_D3_u, 1C13 VCCIO2, 1C15 GPIO1_D4_u, A27 GPIO1_C4_u, A29 GPIO1_C5_d, A30 GPIO1_C1_u, A32 GPIO1_B4_u, A33 GPIO1_C3_u, B27 GPIO1_B5_u, B29 GPIO1_B7_u, B30 GPIO1_C2_u, B32 GPIO1_B6_u, B33 GPIO1_C0_u
part J pins: 1D20 GPIO1_D7_u, 1E19 GPIO2_A1_u, 1E20 GPIO1_D5_u, 1F17 VCCIO3, 1F18 GPIO2_A0_u, 1F19 GPIO1_D6_u, G38 GPIO2_A2_d
part K pins: 1A20 GPIO2_A6_u, 1B20 GPIO2_C4_d, 1C19 GPIO2_A3_u, 1C20 GPIO2_B3_u, 1D18 GPIO2_A5_u, 1D19 GPIO2_C3_d, 1E16 VCCIO4, 1E18 GPIO2_A4_u, A35 GPIO2_B1_d, A37 GPIO2_C0_d, B34 GPIO2_B2_u, B35 GPIO2_A7_u, B36 GPIO2_C1_d, B37 GPIO2_B0_d, B38 GPIO2_C6_d, C37 GPIO2_C2_d, D37 GPIO2_C5_d, D38 GPIO2_B7_d, F37 GPIO2_B5_u, F38 GPIO2_B4_u, G37 GPIO2_B6_u
part L pins: 1N5 VCCIO5_1, 1N6 VCCIO5_2, 1P3 GPIO3_C4_d, 1P4 GPIO3_C5_d, 1T4 GPIO3_B5_d, 1U3 GPIO3_B4_d, 1U4 GPIO3_A6_d, 1U5 GPIO3_A1_d, 1V2 GPIO3_B6_d, 1V3 GPIO3_A7_d, AP3 GPIO3_C2_d, AP4 GPIO3_C1_d, AP5 GPIO3_B7_d, AP6 GPIO3_B3_d, AP7 GPIO3_B1_d, AP9 GPIO3_A5_d, AP10 GPIO3_A3_d, AR2 GPIO3_C3_d, AR4 GPIO3_C0_d, AR6 GPIO3_B2_d, AR7 GPIO3_B0_d, AR9 GPIO3_A4_d, AR10 GPIO3_A2_d
part M pins: 1L1 GPIO4_B6_d, 1L2 GPIO4_B0_d, 1L4 VCCIO6_1, 1L5 VCCIO6_2, 1N1 GPIO4_A7_d, 1N2 GPIO4_A4_d, 1P2 GPIO4_A1_d, 1R1 GPIO4_A2_d, 1R2 GPIO3_D4_d, 1T1 GPIO3_D5_d, 1T2 GPIO3_C6_d, 1U1 GPIO3_C7_d, AB1 GPIO4_C1_d, AB2 GPIO4_C0_d, AC2 GPIO4_B7_d, AD1 GPIO4_B5_d, AE2 GPIO4_B3_d, AF1 GPIO4_B4_d, AF2 GPIO4_B2_d, AG2 GPIO4_B1_d, AH2 GPIO4_A6_d, AJ1 GPIO4_A5_d, AJ2 GPIO4_A3_d, AK2 GPIO4_A0_d, AL1 GPIO3_D7_d, AL2 GPIO3_D6_d, AM1 GPIO3_D3_d, AM2 GPIO3_D2_d, AN2 GPIO3_D1_d, AP1 GPIO3_D0_d
part N pins: 1N8 VCCIO7, 1T6 GPIO4_C6_d, 1U6 GPIO4_C5_d, 1U7 GPIO4_C2_d, 1V5 GPIO4_D1_u, 1V6 GPIO4_C4_d, AP11 GPIO4_D0_u, AP12 GPIO4_C3_d, AR12 GPIO4_C7_u
part O pins: 1A19 SARADC_VIN3, 1B18 SARADC_VIN2, 1C17 SARADC_VIN1, 1D15 OTP_VCC18, 1D16 SARADC_AVDD_1V8, 1D17 SARADC_VIN0
part P pins: 1N9 MIPI_CSI_RX_AVDD_0V9, 1P9 MIPI_CSI_RX_AVDD_1V8, 1U8 MIPI_CSI_RX_CLK1n, 1U9 MIPI_CSI_RX_CLK0n, 1V8 MIPI_CSI_RX_CLK1p, 1V9 MIPI_CSI_RX_CLK0p, AP14 MIPI_CSI_RX_D3n, AP15 MIPI_CSI_RX_D2p, AP17 MIPI_CSI_RX_D1n, AP18 MIPI_CSI_RX_D0p, AR14 MIPI_CSI_RX_D3p, AR15 MIPI_CSI_RX_D2n, AR17 MIPI_CSI_RX_D1p, AR18 MIPI_CSI_RX_D0n
part Q pins: 1N13 HDMI_TX_AVDD_0V9_2, 1N14 HDMI_TX_AVDD_0V9_1, 1P13 HDMI_TX_AVDD_1V8, 1U16 HDMI_TX_REXT, 1V17 HDMI_TX_HPDIN, AP32 HDMI_TX_CLKn, AP33 HDMI_TX_D0p, AP35 HDMI_TX_D1n, AP36 HDMI_TX_D2p, AR32 HDMI_TX_CLKp, AR33 HDMI_TX_D0n, AR35 HDMI_TX_D1p, AR36 HDMI_TX_D2n
part R pins: 1P11 MIPI_DSI_TX0/LVDS_TX0_AVDD_0V9, 1P12 MIPI_DSI_TX0/LVDS_TX0_AVDD_1V8, 1V15 MIPI_DSI_TX0_CLKn/LVDS_TX0_CLKn, 1V16 MIPI_DSI_TX0_CLKp/LVDS_TX0_CLKp, AP26 MIPI_DSI_TX0_D3n/LVDS_TX0_D3n, AP27 MIPI_DSI_TX0_D2p/LVDS_TX0_D2p, AP29 MIPI_DSI_TX0_D1n/LVDS_TX0_D1n, AP30 MIPI_DSI_TX0_D0p/LVDS_TX0_D0p, AR26 MIPI_DSI_TX0_D3p/LVDS_TX0_D3p, AR27 MIPI_DSI_TX0_D2n/LVDS_TX0_D2n, AR29 MIPI_DSI_TX0_D1p/LVDS_TX0_D1p, AR30 MIPI_DSI_TX0_D0n/LVDS_TX0_D0n
part S pins: 1N10 MIPI_DSI_TX1_AVDD_0V9, 1R10 MIPI_DSI_TX1_AVDD_1V8, 1U11 MIPI_DSI_TX1_CLKn, 1V11 MIPI_DSI_TX1_CLKp, AP20 MIPI_DSI_TX1_D3n, AP21 MIPI_DSI_TX1_D2p, AP23 MIPI_DSI_TX1_D1n, AP24 MIPI_DSI_TX1_D0p, AR20 MIPI_DSI_TX1_D3p, AR21 MIPI_DSI_TX1_D2n, AR23 MIPI_DSI_TX1_D1p, AR24 MIPI_DSI_TX1_D0n
part T pins: 1G17 EDP_TX_AVDD_1V8, 1H17 EDP_TX_AVDD_0V9, 1H19 EDP_TX_AUXp, 1H20 EDP_TX_AUXn, J37 EDP_TX_D0p, J38 EDP_TX_D0n, K37 EDP_TX_D1n, K38 EDP_TX_D1p, M37 EDP_TX_D2p, M38 EDP_TX_D2n, N37 EDP_TX_D3p, N38 EDP_TX_D3n
part U pins: 1H16 USB_AVDD1_1V8, 1H18 USB_AVDD1_3V3, 1J17 USB_AVDD1_0V9, 1J19 USB_HOST1_DP, 1J20 USB_HOST1_DM, 1K16 MULTI_PHY_AVDD_0V9, 1K17 MULTI_PHY_AVDD_1V8, 1K19 PCIE20_REFCLKp, 1K20 PCIE20_REFCLKn, AA37 PCIE20_TXp/SATA2_TXp, AA38 PCIE20_TXn/SATA2_TXn, AB37 PCIE20_RXp/SATA2_RXp, AB38 PCIE20_RXn/SATA2_RXn, R37 USB_OTG0_DP, R38 USB_OTG0_DM, T37 USB_OTG0_ID, T38 USB_OTG0_VBUSDET, V37 USB3_HOST1_SSRXn/SATA1_RXn, V38 USB3_HOST1_SSRXp/SATA1_RXp, W37 USB3_HOST1_SSTXp/SATA1_TXp, W38 USB3_HOST1_SSTXn/SATA1_TXn
part V pins: 1J2 USB_AVDD2_3V3, 1J3 USB_AVDD2_1V8, 1J4 USB_AVDD2_0V9, V1 USB_HOST2_DM, V2 USB_HOST2_DP, Y1 USB_HOST3_DM, Y2 USB_HOST3_DP

## SPACER
designator SS?
CLASS: IC
pins: 1 NC_1

## TCS4525
designator U?
footprint WLCSP-20
pins: A1 VSEL, A2 EN, A3 SCL, A4 VOUT, B1 SDA, B2 GND1, B3 GND2, B4 AGND, C1 GND3, C2 GND4, C3 GND5, C4 GND6, D1 VIN_1, D2 VIN_2, D3 SW_1, D4 SW_2, E1 VIN_3, E2 VIN_4, E3 SW_3, E4 SW_4

## TitleBlock_YHSCH
designator *  OrgName: 东莞野火电子技术有限公司  Page Number: 1  (hidden comment: *)  (graphical)

## TP6327GS6
designator U?
pins: 1 GND, 2 SW, 3 VIN, 4 FB, 5 EN, 6 BOOT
